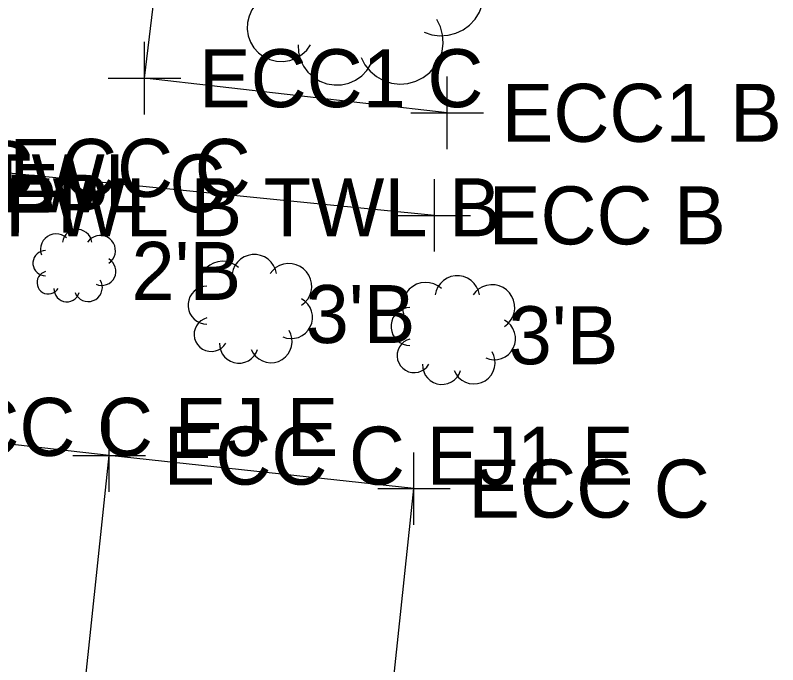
# Model space of a CAD drawing. Extents: x 1363693 to 1365209, y 422201 to 424153.
# Drawn here: x 1364320.23 to 1364341.26, y 423332.82 to 423350.74 of the extents above; entities that cross this region are included whole.
import ezdxf

# ---------------------------------------------------------------- set-up
doc = ezdxf.new("R2010")
doc.units = 0
for name, color, linetype in [('PV_X_Driveway', 7, 'Continuous'), ('PV_X_Joint', 7, 'Continuous'), ('SV_X_Random_Point', 7, 'Continuous'), ('SV_X_Shot_Marker', 7, 'Continuous'), ('VG_X_Cells', 7, 'Continuous'), ('VG_X_Text', 7, 'Continuous')]:
    doc.layers.add(name, color=color, linetype=linetype)

msp = doc.modelspace()

# ---------------------------------------------------------------- linework, layer by layer
at = {"layer": 'PV_X_Driveway'}
for points in [[(1364331.792, 423345.218), (1364318.569, 423346.527), (1364322.532, 423371.799)], [(1364332.146, 423348.047), (1364323.796, 423349.002), (1364325.909, 423366.51), (1364326.847, 423366.42)], [(1364306.082, 423330.285), (1364314.808, 423329.408), (1364321.777, 423328.694), (1364330.192, 423327.953), (1364331.23, 423337.679), (1364322.823, 423338.59), (1364315.875, 423339.383), (1364307.079, 423340.044)]]:
    msp.add_lwpolyline(points, dxfattribs=at)
at = {"layer": 'PV_X_Joint'}
msp.add_line((1364321.777, 423328.694), (1364322.823, 423338.59), dxfattribs=at)
at = {"layer": 'SV_X_Shot_Marker'}
for p, q in [((1364323.796, 423348.002), (1364323.796, 423350.002)), ((1364322.796, 423349.002), (1364324.796, 423349.002)), ((1364332.146, 423347.047), (1364332.146, 423349.047)), ((1364331.146, 423348.047), (1364333.146, 423348.047)), ((1364331.792, 423344.218), (1364331.792, 423346.218)), ((1364330.792, 423345.218), (1364332.792, 423345.218)), ((1364322.823, 423337.59), (1364322.823, 423339.59)), ((1364321.823, 423338.59), (1364323.823, 423338.59)), ((1364331.23, 423336.679), (1364331.23, 423338.679)), ((1364330.23, 423337.679), (1364332.23, 423337.679))]:
    msp.add_line(p, q, dxfattribs=at)
at = {"layer": 'VG_X_Cells'}
for points in [[(1364331.515, 423350.273), (1364331.726, 423350.203), (1364331.946, 423350.174), (1364332.168, 423350.188), (1364332.384, 423350.243), (1364332.585, 423350.338), (1364332.764, 423350.469), (1364332.916, 423350.632), (1364333.034, 423350.82), (1364333.114, 423351.028), (1364333.153, 423351.246), (1364333.15, 423351.469), (1364333.106, 423351.687), (1364333.02, 423351.892), (1364332.898, 423352.078), (1364332.743, 423352.237), (1364332.56, 423352.363)], [(1364327.335, 423351.318), (1364327.162, 423351.255), (1364327.004, 423351.159), (1364326.869, 423351.034), (1364326.76, 423350.885), (1364326.682, 423350.718), (1364326.638, 423350.539), (1364326.63, 423350.355), (1364326.658, 423350.173), (1364326.722, 423349.999), (1364326.817, 423349.842), (1364326.942, 423349.706), (1364327.09, 423349.596), (1364327.258, 423349.518), (1364327.437, 423349.474), (1364327.621, 423349.466), (1364327.803, 423349.494), (1364327.977, 423349.557), (1364328.134, 423349.652), (1364328.271, 423349.777), (1364328.38, 423349.925)], [(1364329.773, 423349.577), (1364329.878, 423349.375), (1364330.02, 423349.196), (1364330.193, 423349.049), (1364330.392, 423348.938), (1364330.609, 423348.867), (1364330.835, 423348.84), (1364331.062, 423348.857), (1364331.282, 423348.918), (1364331.485, 423349.019), (1364331.666, 423349.159), (1364331.815, 423349.33), (1364331.929, 423349.528), (1364332.003, 423349.743), (1364332.033, 423349.969), (1364332.02, 423350.196), (1364331.962, 423350.417), (1364331.863, 423350.622)], [(1364328.032, 423349.925), (1364328.043, 423349.72), (1364328.094, 423349.521), (1364328.181, 423349.335), (1364328.303, 423349.169), (1364328.455, 423349.03), (1364328.63, 423348.922), (1364328.822, 423348.85), (1364329.025, 423348.816), (1364329.231, 423348.822), (1364329.431, 423348.867), (1364329.619, 423348.95), (1364329.788, 423349.067), (1364329.932, 423349.214), (1364330.044, 423349.386), (1364330.122, 423349.577)], [(1364321.649, 423344.596), (1364321.584, 423344.645), (1364321.511, 423344.68), (1364321.432, 423344.702), (1364321.35, 423344.708), (1364321.269, 423344.698), (1364321.191, 423344.674), (1364321.12, 423344.635), (1364321.056, 423344.584), (1364321.004, 423344.521), (1364320.964, 423344.45), (1364320.938, 423344.373), (1364320.928, 423344.292), (1364320.933, 423344.21), (1364320.953, 423344.131)], [(1364322.346, 423344.48), (1364322.327, 423344.555), (1364322.295, 423344.626), (1364322.25, 423344.69), (1364322.193, 423344.744), (1364322.128, 423344.786), (1364322.055, 423344.815), (1364321.979, 423344.83), (1364321.9, 423344.83), (1364321.824, 423344.815), (1364321.751, 423344.786), (1364321.686, 423344.744), (1364321.629, 423344.69), (1364321.584, 423344.626), (1364321.551, 423344.555), (1364321.533, 423344.48)], [(1364322.81, 423343.899), (1364322.871, 423343.948), (1364322.921, 423344.007), (1364322.96, 423344.075), (1364322.985, 423344.149), (1364322.996, 423344.225), (1364322.993, 423344.303), (1364322.975, 423344.379), (1364322.944, 423344.45), (1364322.9, 423344.515), (1364322.845, 423344.57), (1364322.781, 423344.613), (1364322.71, 423344.645), (1364322.634, 423344.662), (1364322.556, 423344.665), (1364322.479, 423344.654), (1364322.406, 423344.629), (1364322.338, 423344.59), (1364322.279, 423344.54), (1364322.23, 423344.48)], [(1364321.069, 423344.247), (1364321.005, 423344.241), (1364320.943, 423344.224), (1364320.885, 423344.195), (1364320.834, 423344.156), (1364320.791, 423344.109), (1364320.757, 423344.054), (1364320.734, 423343.994), (1364320.722, 423343.931), (1364320.722, 423343.867), (1364320.734, 423343.804), (1364320.757, 423343.744), (1364320.791, 423343.689), (1364320.834, 423343.642), (1364320.885, 423343.603), (1364320.943, 423343.574), (1364321.005, 423343.557), (1364321.069, 423343.551)], [(1364327.435, 423343.61), (1364327.408, 423343.724), (1364327.359, 423343.831), (1364327.291, 423343.926), (1364327.207, 423344.007), (1364327.108, 423344.07), (1364326.999, 423344.114), (1364326.884, 423344.136), (1364326.767, 423344.136), (1364326.652, 423344.114), (1364326.543, 423344.07), (1364326.445, 423344.007), (1364326.36, 423343.926), (1364326.292, 423343.831), (1364326.244, 423343.724), (1364326.216, 423343.61)], [(1364322.462, 423343.318), (1364322.532, 423343.295), (1364322.606, 423343.285), (1364322.68, 423343.29), (1364322.752, 423343.308), (1364322.819, 423343.34), (1364322.878, 423343.384), (1364322.929, 423343.438), (1364322.968, 423343.501), (1364322.995, 423343.57), (1364323.008, 423343.643), (1364323.007, 423343.717), (1364322.992, 423343.79), (1364322.964, 423343.858), (1364322.923, 423343.92), (1364322.871, 423343.973), (1364322.81, 423344.015)], [(1364326.39, 423343.784), (1364326.292, 423343.858), (1364326.182, 423343.912), (1364326.064, 423343.944), (1364325.942, 423343.953), (1364325.82, 423343.939), (1364325.704, 423343.902), (1364325.596, 423343.844), (1364325.501, 423343.767), (1364325.422, 423343.673), (1364325.362, 423343.566), (1364325.324, 423343.45), (1364325.308, 423343.329), (1364325.315, 423343.206), (1364325.345, 423343.088)], [(1364328.132, 423342.74), (1364328.223, 423342.813), (1364328.298, 423342.902), (1364328.356, 423343.003), (1364328.394, 423343.114), (1364328.411, 423343.229), (1364328.406, 423343.346), (1364328.38, 423343.46), (1364328.333, 423343.566), (1364328.267, 423343.663), (1364328.184, 423343.745), (1364328.088, 423343.811), (1364327.981, 423343.858), (1364327.867, 423343.884), (1364327.751, 423343.889), (1364327.635, 423343.872), (1364327.525, 423343.834), (1364327.424, 423343.776), (1364327.335, 423343.701), (1364327.261, 423343.61)], [(1364321.069, 423343.667), (1364321.011, 423343.646), (1364320.958, 423343.614), (1364320.913, 423343.572), (1364320.877, 423343.522), (1364320.851, 423343.467), (1364320.836, 423343.407), (1364320.834, 423343.346), (1364320.843, 423343.285), (1364320.864, 423343.227), (1364320.896, 423343.175), (1364320.938, 423343.129), (1364320.987, 423343.093), (1364321.043, 423343.067), (1364321.103, 423343.052), (1364321.164, 423343.049), (1364321.225, 423343.059), (1364321.283, 423343.08), (1364321.335, 423343.111), (1364321.381, 423343.153), (1364321.417, 423343.202)], [(1364321.881, 423343.086), (1364321.916, 423343.019), (1364321.964, 423342.959), (1364322.021, 423342.91), (1364322.088, 423342.873), (1364322.16, 423342.85), (1364322.235, 423342.841), (1364322.311, 423342.846), (1364322.384, 423342.867), (1364322.452, 423342.9), (1364322.512, 423342.947), (1364322.562, 423343.004), (1364322.6, 423343.07), (1364322.625, 423343.142), (1364322.635, 423343.217), (1364322.63, 423343.293), (1364322.611, 423343.366), (1364322.578, 423343.435)], [(1364333.033, 423343.025), (1364333.006, 423343.139), (1364332.957, 423343.246), (1364332.889, 423343.341), (1364332.805, 423343.422), (1364332.706, 423343.485), (1364332.597, 423343.529), (1364332.482, 423343.551), (1364332.365, 423343.551), (1364332.25, 423343.529), (1364332.141, 423343.485), (1364332.043, 423343.422), (1364331.958, 423343.341), (1364331.89, 423343.246), (1364331.842, 423343.139), (1364331.814, 423343.025)], [(1364325.52, 423343.262), (1364325.423, 423343.253), (1364325.331, 423343.227), (1364325.244, 423343.184), (1364325.168, 423343.126), (1364325.103, 423343.054), (1364325.052, 423342.972), (1364325.017, 423342.882), (1364324.999, 423342.788), (1364324.999, 423342.691), (1364325.017, 423342.597), (1364325.052, 423342.507), (1364325.103, 423342.425), (1364325.168, 423342.353), (1364325.244, 423342.295), (1364325.331, 423342.252), (1364325.423, 423342.226), (1364325.52, 423342.217)], [(1364331.988, 423343.199), (1364331.89, 423343.273), (1364331.78, 423343.327), (1364331.662, 423343.359), (1364331.54, 423343.368), (1364331.418, 423343.354), (1364331.302, 423343.317), (1364331.194, 423343.259), (1364331.099, 423343.182), (1364331.02, 423343.088), (1364330.96, 423342.981), (1364330.922, 423342.865), (1364330.906, 423342.744), (1364330.913, 423342.621), (1364330.943, 423342.503)], [(1364333.73, 423342.155), (1364333.821, 423342.228), (1364333.896, 423342.317), (1364333.954, 423342.418), (1364333.992, 423342.529), (1364334.009, 423342.644), (1364334.004, 423342.761), (1364333.978, 423342.875), (1364333.931, 423342.981), (1364333.865, 423343.078), (1364333.782, 423343.16), (1364333.686, 423343.226), (1364333.579, 423343.273), (1364333.465, 423343.299), (1364333.349, 423343.304), (1364333.233, 423343.287), (1364333.123, 423343.249), (1364333.022, 423343.191), (1364332.933, 423343.116), (1364332.859, 423343.025)], [(1364321.301, 423343.202), (1364321.305, 423343.134), (1364321.322, 423343.068), (1364321.351, 423343.006), (1364321.391, 423342.95), (1364321.442, 423342.904), (1364321.5, 423342.868), (1364321.564, 423342.844), (1364321.632, 423342.833), (1364321.701, 423342.835), (1364321.767, 423342.85), (1364321.83, 423342.877), (1364321.886, 423342.916), (1364321.934, 423342.965), (1364321.972, 423343.023), (1364321.998, 423343.086)], [(1364327.609, 423341.869), (1364327.715, 423341.834), (1364327.825, 423341.819), (1364327.936, 423341.826), (1364328.044, 423341.853), (1364328.144, 423341.901), (1364328.234, 423341.966), (1364328.31, 423342.048), (1364328.369, 423342.142), (1364328.409, 423342.246), (1364328.429, 423342.355), (1364328.427, 423342.466), (1364328.405, 423342.575), (1364328.362, 423342.678), (1364328.301, 423342.771), (1364328.223, 423342.85), (1364328.132, 423342.914)], [(1364331.118, 423342.677), (1364331.021, 423342.668), (1364330.929, 423342.642), (1364330.842, 423342.599), (1364330.766, 423342.541), (1364330.701, 423342.469), (1364330.65, 423342.387), (1364330.615, 423342.297), (1364330.597, 423342.203), (1364330.597, 423342.106), (1364330.615, 423342.012), (1364330.65, 423341.922), (1364330.701, 423341.84), (1364330.766, 423341.768), (1364330.842, 423341.71), (1364330.929, 423341.667), (1364331.021, 423341.641), (1364331.118, 423341.632)], [(1364325.52, 423342.391), (1364325.433, 423342.359), (1364325.354, 423342.312), (1364325.286, 423342.249), (1364325.232, 423342.175), (1364325.193, 423342.091), (1364325.171, 423342.002), (1364325.167, 423341.909), (1364325.181, 423341.818), (1364325.213, 423341.732), (1364325.261, 423341.653), (1364325.323, 423341.585), (1364325.397, 423341.53), (1364325.481, 423341.491), (1364325.57, 423341.469), (1364325.662, 423341.465), (1364325.754, 423341.479), (1364325.84, 423341.51), (1364325.919, 423341.558), (1364325.987, 423341.62), (1364326.042, 423341.695)], [(1364333.207, 423341.284), (1364333.313, 423341.249), (1364333.423, 423341.234), (1364333.534, 423341.241), (1364333.642, 423341.268), (1364333.742, 423341.316), (1364333.832, 423341.381), (1364333.908, 423341.463), (1364333.967, 423341.557), (1364334.007, 423341.661), (1364334.027, 423341.77), (1364334.025, 423341.881), (1364334.003, 423341.99), (1364333.96, 423342.093), (1364333.899, 423342.186), (1364333.821, 423342.265), (1364333.73, 423342.329)], [(1364326.739, 423341.52), (1364326.791, 423341.419), (1364326.862, 423341.33), (1364326.949, 423341.256), (1364327.048, 423341.201), (1364327.156, 423341.166), (1364327.27, 423341.152), (1364327.383, 423341.161), (1364327.493, 423341.191), (1364327.595, 423341.242), (1364327.685, 423341.311), (1364327.76, 423341.397), (1364327.817, 423341.496), (1364327.853, 423341.604), (1364327.869, 423341.716), (1364327.862, 423341.83), (1364327.833, 423341.94), (1364327.784, 423342.043)], [(1364331.118, 423341.806), (1364331.031, 423341.774), (1364330.952, 423341.727), (1364330.884, 423341.664), (1364330.83, 423341.59), (1364330.791, 423341.506), (1364330.769, 423341.417), (1364330.765, 423341.324), (1364330.779, 423341.233), (1364330.811, 423341.147), (1364330.859, 423341.068), (1364330.921, 423341), (1364330.995, 423340.945), (1364331.079, 423340.906), (1364331.168, 423340.884), (1364331.26, 423340.88), (1364331.352, 423340.894), (1364331.438, 423340.925), (1364331.517, 423340.973), (1364331.585, 423341.035), (1364331.64, 423341.11)], [(1364325.868, 423341.695), (1364325.874, 423341.592), (1364325.899, 423341.492), (1364325.943, 423341.399), (1364326.004, 423341.317), (1364326.079, 423341.247), (1364326.167, 423341.193), (1364326.263, 423341.157), (1364326.365, 423341.14), (1364326.467, 423341.143), (1364326.568, 423341.166), (1364326.662, 423341.207), (1364326.746, 423341.265), (1364326.818, 423341.339), (1364326.874, 423341.425), (1364326.913, 423341.52)], [(1364332.337, 423340.935), (1364332.389, 423340.834), (1364332.46, 423340.745), (1364332.547, 423340.671), (1364332.646, 423340.616), (1364332.754, 423340.581), (1364332.868, 423340.567), (1364332.981, 423340.576), (1364333.091, 423340.606), (1364333.193, 423340.657), (1364333.283, 423340.726), (1364333.358, 423340.812), (1364333.415, 423340.911), (1364333.451, 423341.019), (1364333.467, 423341.131), (1364333.46, 423341.245), (1364333.431, 423341.355), (1364333.382, 423341.458)], [(1364331.466, 423341.11), (1364331.472, 423341.007), (1364331.497, 423340.907), (1364331.541, 423340.814), (1364331.602, 423340.732), (1364331.677, 423340.662), (1364331.765, 423340.608), (1364331.861, 423340.572), (1364331.963, 423340.555), (1364332.065, 423340.558), (1364332.166, 423340.581), (1364332.26, 423340.622), (1364332.344, 423340.68), (1364332.416, 423340.754), (1364332.472, 423340.84), (1364332.511, 423340.935)]]:
    msp.add_lwpolyline(points, dxfattribs=at)

# ---------------------------------------------------------------- texts
at = {"layer": 'SV_X_Random_Point'}
for s, p in [('TWL C', (1364314.071, 423345.666)), ('TWL C', (1364319.375, 423345.3)), ('FWL B TWL B', (1364319.954, 423344.642))]:
    msp.add_text(s, height=1.6, dxfattribs=at).set_placement(p)
at = {"layer": 'SV_X_Shot_Marker'}
for s, p in [('ECC1 C', (1364325.296, 423348.202)), ('ECC1 B', (1364333.646, 423347.247)), ('ECC C', (1364320.069, 423345.727)), ('INV4CPP', (1364313.659, 423344.737)), ('ECC B', (1364333.292, 423344.418)), ('ECC C EJ E', (1364317.375, 423338.583)), ('ECC C EJ1 E', (1364324.323, 423337.79)), ('ECC C', (1364332.73, 423336.879))]:
    msp.add_text(s, height=1.6, dxfattribs=at).set_placement(p)
at = {"layer": 'VG_X_Text'}
for s, p in [("2'B", (1364323.439, 423342.886)), ("3'B", (1364328.243, 423341.696)), ("3'B", (1364333.841, 423341.111))]:
    msp.add_text(s, height=1.6, dxfattribs=at).set_placement(p)

doc.saveas('drawing.dxf')
